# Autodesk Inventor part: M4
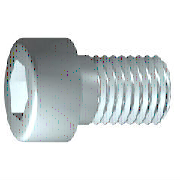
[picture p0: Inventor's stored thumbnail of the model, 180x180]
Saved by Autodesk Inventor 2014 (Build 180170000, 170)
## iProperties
IsCustomPart: 0
Created: 2014-10
Part Number: M4
Material: 강철, 연강
Description: 6각머리 태핑 나사
Document SubType Name: Modeling
Standard: KS B 1003
Designer: KYOUNG IL JANG
Standards Organization: KS
Language: ko-KR
Size Designation: M 4 x 10
Categories: <MemberInstance><Categories><Category DisplayName="조임쇠" InternalName="e4da775c-781d-43d5-af7c-5136215cf5a6" Mnemonic="FSTN"><Category DisplayName="볼트" InternalN
Density: 7.86 g/cm^3
Mass: 2.0371 g
Surface Area: 3.0572 cm^2
Volume: 0.259174 cm^3
Appearance: 검은색 캐스트
Author: SeoGD™ [www.esajin.kr]
Revision Number: 1
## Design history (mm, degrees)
sketch "스케치1"
  geometry: L1 (-1, 0)-(10, 0); L2 (10, 0)-(10, 2); L3 (10, 2)-(1.75, 2); L4 (1.75, 2)-(1.32, 2); L5 (1.32, 2)-(0, 2); L6 (0, 2)-(0, 3.5); L7 (0, 3.5)-(-4, 3.5); L8 (-4, 3.5)-(-4, 1.732); L9 (-4, 1.732)-(-2, 1.732); L10 (-2, 1.732)-(-1, 0); L11 (-6.8, 0)-(12.8, 0) reference; L12 (0, -0.7)-(0, 4.2) reference; L13 (1.75, 2)-(0, 2)
  constraints: 22 end point, 6 parallel, 2 collinear, 2 perpendicular, 1 horizontal, 1 point on line
  dimensions: "d1" = 8.25 distance from line of L3.end L2 (= GEL); "d2" = 0.42952 distance of L4.end L3.end (computed from GAL); "d3" = 4 distance between parallel lines of L8 L6 (= KOH); "d4" = 2 distance of L8.end L9.end (= INTI); "d5" = 60 deg angle of L10 L1; "d6" = 4 diameter of L3 L1 (= GD); "d7" = 4 diameter of L5 L1 (= BDM); "d8" = 3.4641 diameter of L9 L1 (= 1.1547 x SW); "d9" = 7 diameter of L7 L1 (= KOD); "d26" = 10 distance between parallel lines of L12 L2 (= NLG)
revolve "본체" sketch "스케치1" stored, may be unused: angle "d10" = 90 deg
sketch "스케치2"
  geometry: L1 (0, -4.9)-(0, 4.9) reference; L2 (-4.9, 0)-(4.9, 0) reference; L3 (1.732, 0)-(0.866, -1.5); L4 (0.866, -1.5)-(-0.866, -1.5); L5 (-0.866, -1.5)-(-1.732, 0); L6 (-1.732, 0)-(-0.866, 1.5); L7 (-0.866, 1.5)-(0.866, 1.5); L8 (0.866, 1.5)-(1.732, 0); 2 further points
  constraints: 12 end point, 1 coincident, 1 horizontal alignment, 1 point on line, 12 other
extrude "슬롯" join sketch "스케치2" stored distance "d11" = 10; taper "d12" = 0 deg
workplane "Work Plane1"
fillet "Fillet2" dims "d30" = 0.1 (= R)
body "Solid1"
fillet "모깎기1" dims "d17" = 0.4 (= RR)
feature "스레드" dims "d13" = 8.25 (= GEL), "d14" = 0
chamfer "모따기1" distance "d15" = 0.42941 (= -0.5 x SPD + 0.5 x GD); stored, may be unused: second distance "d16" = 0.42941 (= GUL), angle "d27" = 45 deg
other parameters: "GD" = 4 (= NND) [user parameter; used in 2 equation terms], "NLG" = 10 [user parameter; used in 1 equation term], "GEL" = 8.25 [user parameter; used in 2 equation terms], "KOD" = 7 [user parameter; used in 1 equation term], "KOH" = 4 [user parameter; used in 1 equation term], "INTI" = 2 [user parameter; used in 1 equation term], "GAL" = 0.42941 (= 0.61345 x PTC) [user parameter; used in 1 equation term], "GUL" = 0.42941 (= 0.61345 x PTC) [user parameter; used in 1 equation term], "BDM" = 4 (= NND) [user parameter; used in 1 equation term], "SW" = 3 [user parameter; used in 2 equation terms], "RR" = 0.4 [user parameter; used in 1 equation term], "SPD" = 3.14117 (= NND - 1.2269 x PTC) [user parameter; used in 1 equation term], "d19" = 0, "d28" = 0, "d29" = 0, "R" = 0.1 [user parameter; used in 1 equation term], "PHH" = 0.2 [user parameter], "GD1" = 3.14117 (= THREADDIA - 1.2269 x PTC) [user parameter], "THREADDIA" = 4 [user parameter; used in 1 equation term], "FAWI" = 45 deg [user parameter], "TPU" = 14.28571 (computed from PTC) [user parameter], "PTC" = 0.7 [user parameter; used in 5 equation terms], "NND" = 4 [user parameter; used in 3 equation terms], "TOA" = 30 deg [user parameter], "E0" = 3.465 (= 1.155 x SW) [user parameter]
